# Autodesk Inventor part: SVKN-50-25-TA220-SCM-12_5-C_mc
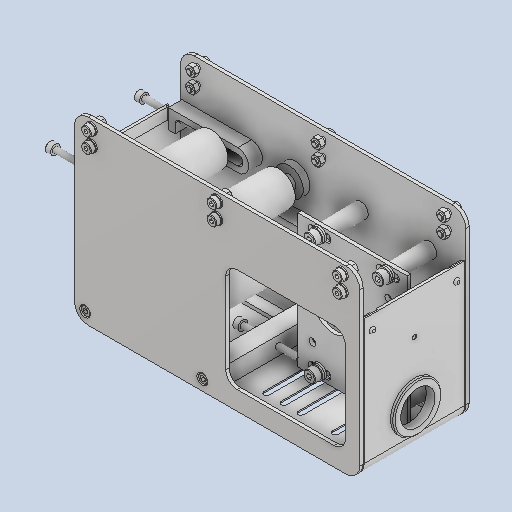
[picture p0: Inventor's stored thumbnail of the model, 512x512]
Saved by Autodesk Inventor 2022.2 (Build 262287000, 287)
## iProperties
Created: 2024-10
Part Number: SVKN-50-25-TA220-SCM-12_5-C_mc
Material: Generico
Document SubType Name: Modeling
Designer: 18907419
Density: 1 g/cm^3
Appearance: Default
Author: 18907419
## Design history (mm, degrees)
feature "Solido1"
node "Solido2"
